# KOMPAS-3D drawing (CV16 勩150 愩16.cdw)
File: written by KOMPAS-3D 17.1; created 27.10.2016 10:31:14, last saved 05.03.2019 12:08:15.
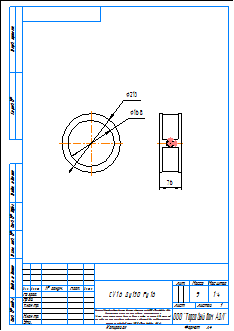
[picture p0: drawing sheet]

Sheet 1: A4, portrait

Title block, sheet 1: name: CV16 Ду150 Ру16; material: Сталь 20  ГОСТ 1050-88; mass: 9; sheets: 1; sheet format: A4; stored path: \\adlc.lan\data\АДЛ_ПКД\3D-модели\ADL production\Клапаны обратные ГРАНЛОК\CV16\KOMPAS 2D\CV16 Ду150 Ру16.cdw

Views: Вид 1, Проекционный вид 2
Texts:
  Klimkovich
  ADL
  Рама для чертежей
  Лит-Масса-Масштаб
  Материал-Предприятие
  Масштаб
  Изм.
  Лист
  № докум.
  Подп.
  Дата
  Лит.
  Разраб.
  Пров.
  Т.контр.
  Листов
  Внимание! Данный продукт является объектом авторского права ООО «Торговый Дом АДЛ».
  Запрещается изменение, копирование, распространение
  (в том числе путем копирования на другие сайты и ресурсы в Интернете)
  или любое иное использование информации и объектов без предварительного
  согласия правообладателя (ООО «Торговый Дом АДЛ»).
  Н.контр.
  Утв.
  ООО "Торговый дом АДЛ"
  Изменение
  Номер документа
  Подпись
  Обозначение документа
  Наименование изделия
  Масса изделия по ГОСТ 2.109-73
  Порядковый номер листа
  Общее количество листов в документе
  Характер работы, выполненной лицом, подписавшим документ
  Наименование или индекс предприятия, выпускающего документ
  Инв. № подл.
  Подп. и дата
  Взам. инв. №
  Инв. № дубл.
  Инвентарный номер подлинника по ГОСТ 2.501-68
  Подпись принявшего подлинник в отдел технической документации
  Инвентарный номер подлинника, взамен которого выпущен данный подлинник
  Инвентарный номер дубликата по ГОСТ 2.502-68
  Подпись принявшего дубликат в отдел технической документации
  Справ. №
  Перв. примен.
  Обозначение документа, взамен или на основании которого выпущен данный документ
  Обозначение документа, в котором впервые записан данный документ
  Подпись лица, копировавшего чертеж
  Обозначение формата листа
  !Рама для чертежа
Dimensions and other numbers on the sheet: 213; 168; 76; 1:4; 1; 9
